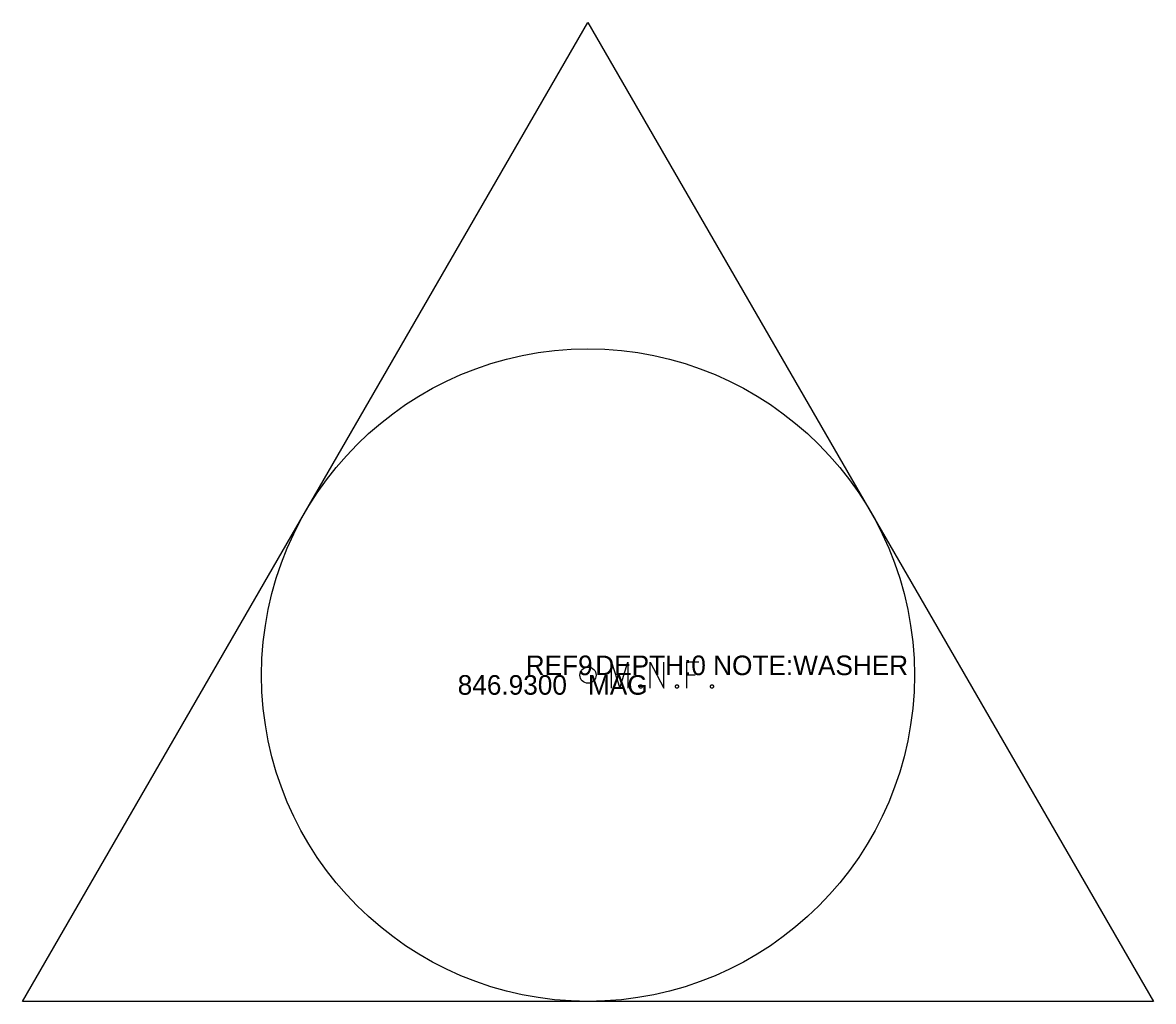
# Model space of a CAD drawing. Extents: x 1785178 to 1804417, y 483851 to 522189.
# Drawn here: x 1800289.457 to 1800292.921, y 494581.078 to 494584.078 of the extents above; entities that cross this region are included whole.
import ezdxf

# ---------------------------------------------------------------- set-up
doc = ezdxf.new("R2010")
doc.units = 0
for name, color, linetype in [('SV_Control_Point', 7, 'Continuous'), ('SV_X_Control_Cells_Found', 7, 'Continuous'), ('SV_X_Text_Comment', 7, 'Continuous'), ('SV_X_Text_Description', 7, 'Continuous'), ('SV_X_Text_Elevation', 7, 'Continuous'), ('SV_X_Text_Name', 7, 'Continuous')]:
    doc.layers.add(name, color=color, linetype=linetype)

msp = doc.modelspace()

# ---------------------------------------------------------------- linework, layer by layer
at = {"layer": 'SV_Control_Point'}
for p, q in [((1800289.4569, 494581.078), (1800291.189, 494584.078)), ((1800291.189, 494584.078), (1800292.9211, 494581.078)), ((1800291.189, 494582.078), (1800291.189, 494582.078)), ((1800292.9211, 494581.078), (1800289.4569, 494581.078))]:
    msp.add_line(p, q, dxfattribs=at)
msp.add_circle((1800291.189, 494582.078), 1, dxfattribs=at)
at = {"layer": 'SV_X_Control_Cells_Found'}
for points in [[(1800291.261, 494582.0376), (1800291.261, 494582.1176), (1800291.2864, 494582.0376), (1800291.3106, 494582.1176), (1800291.3106, 494582.0376)], [(1800291.3795, 494582.0376), (1800291.3795, 494582.1176), (1800291.4209, 494582.0376), (1800291.4209, 494582.1176)], [(1800291.5283, 494582.1176), (1800291.4903, 494582.1176), (1800291.4903, 494582.0376)], [(1800291.4903, 494582.0785), (1800291.5173, 494582.0785)], [(1800291.3492, 494582.0483), (1800291.352, 494582.0483), (1800291.3536, 494582.047), (1800291.3553, 494582.0445), (1800291.3553, 494582.0414), (1800291.3536, 494582.0388), (1800291.352, 494582.0376), (1800291.3492, 494582.0376), (1800291.3475, 494582.0388), (1800291.3459, 494582.0414), (1800291.3459, 494582.0445), (1800291.3475, 494582.047), (1800291.3492, 494582.0483)], [(1800291.46, 494582.0483), (1800291.4627, 494582.0483), (1800291.4644, 494582.047), (1800291.466, 494582.0445), (1800291.466, 494582.0414), (1800291.4644, 494582.0388), (1800291.4627, 494582.0376), (1800291.46, 494582.0376), (1800291.4583, 494582.0388), (1800291.4567, 494582.0414), (1800291.4567, 494582.0445), (1800291.4583, 494582.047), (1800291.46, 494582.0483)], [(1800291.5675, 494582.0483), (1800291.5702, 494582.0483), (1800291.5719, 494582.047), (1800291.5735, 494582.0445), (1800291.5735, 494582.0414), (1800291.5719, 494582.0388), (1800291.5702, 494582.0376), (1800291.5675, 494582.0376), (1800291.5658, 494582.0388), (1800291.5641, 494582.0414), (1800291.5641, 494582.0445), (1800291.5658, 494582.047), (1800291.5675, 494582.0483)]]:
    msp.add_lwpolyline(points, dxfattribs=at)
msp.add_circle((1800291.189, 494582.078), 0.0249, dxfattribs=at)

# ---------------------------------------------------------------- texts
at = {"layer": 'SV_X_Text_Comment'}
msp.add_text('MAG', height=0.06, dxfattribs=at).set_placement((1800291.189, 494582.018))
at = {"layer": 'SV_X_Text_Description'}
msp.add_text(' DEPTH:0 NOTE:WASHER', height=0.06, dxfattribs=at).set_placement((1800291.189, 494582.078))
at = {"layer": 'SV_X_Text_Elevation'}
msp.add_text('846.9300', height=0.06, dxfattribs=at).set_placement((1800290.7898, 494582.018))
at = {"layer": 'SV_X_Text_Name'}
msp.add_text('REF9', height=0.06, dxfattribs=at).set_placement((1800290.9982, 494582.078))

doc.saveas('drawing.dxf')
